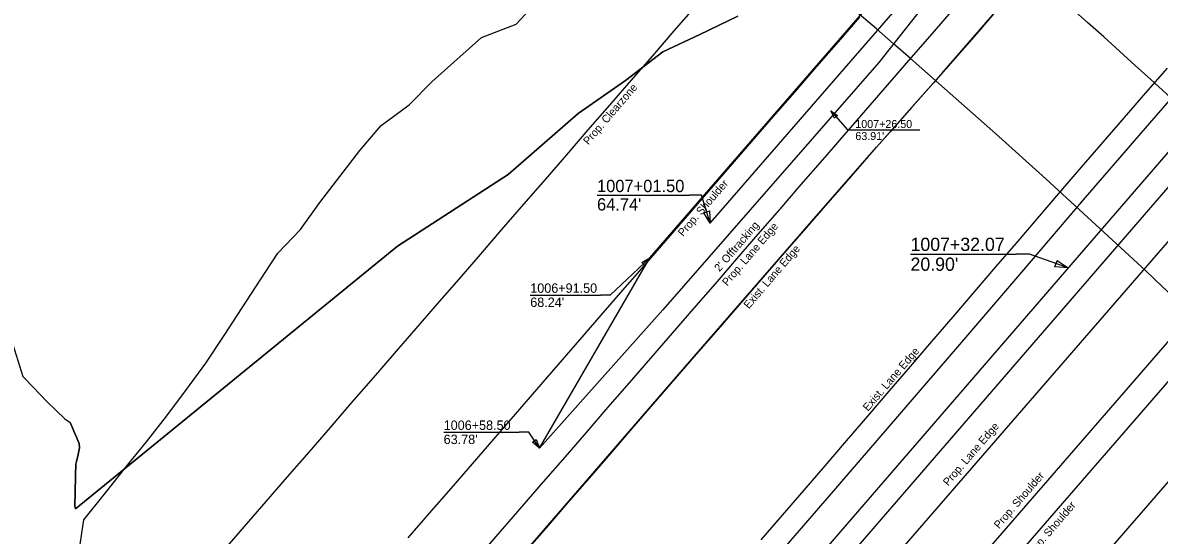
# Model space of a CAD drawing. Extents: x 1006695 to 1009377, y 1883329 to 1886115.
# Drawn here: x 1007700.6 to 1007873.9, y 1884679.4 to 1884757.7 of the extents above; entities that cross this region are included whole.
import ezdxf

# ---------------------------------------------------------------- set-up
doc = ezdxf.new("R2010")
doc.units = 0
for name, color, linetype in [('B_Hatch', 7, 'Continuous'), ('R_I-30 Information', 7, 'Continuous'), ('R_No Plot', 7, 'Continuous'), ('R_Prop Const Limits Cut', 7, 'Continuous'), ('R_Prop EOL', 7, 'Continuous'), ('R_Prop EOS I-30', 7, 'Continuous'), ('R_Prop I-30 Guardrail', 7, 'Continuous')]:
    doc.layers.add(name, color=color, linetype=linetype)

msp = doc.modelspace()

# ---------------------------------------------------------------- linework, layer by layer
at = {"layer": 'B_Hatch'}
for points in [[(1007646.47, 1884785.83), (1007650.32, 1884781.08), (1007657.13, 1884773.48), (1007664.19, 1884766.21), (1007671.31, 1884759.02), (1007678.48, 1884751.9), (1007684.26, 1884742.9), (1007685.68, 1884740.68), (1007687.7, 1884737.51), (1007689.66, 1884734.43), (1007695.24, 1884726.6), (1007697.29, 1884714.24), (1007700.6, 1884703.69), (1007700.97, 1884703.29), (1007704.31, 1884699.79), (1007707.03, 1884697.22), (1007707.84, 1884696.66)], [(1007707.84, 1884696.66), (1007708.2, 1884695.83), (1007708.4, 1884695.35), (1007708.6, 1884694.87), (1007708.81, 1884694.39), (1007709.01, 1884693.91), (1007709.21, 1884693.43), (1007709.27, 1884692.78), (1007709.03, 1884691.74), (1007708.79, 1884690.71), (1007708.7, 1884690.29), (1007708.68, 1884689.84), (1007708.66, 1884689.09), (1007708.65, 1884688.33), (1007708.63, 1884687.58), (1007708.61, 1884686.83), (1007708.59, 1884686.07), (1007708.57, 1884685.32), (1007708.54, 1884684.51), (1007708.54, 1884684.41), (1007708.54, 1884684.3), (1007708.54, 1884684.2), (1007708.53, 1884684.09), (1007708.53, 1884683.99), (1007708.53, 1884683.88), (1007708.63, 1884683.47), (1007757.72, 1884723.55), (1007774.58, 1884734.51), (1007785.28, 1884743.83), (1007792.48, 1884748.84), (1007798.18, 1884753.24), (1007803.81, 1884755.88), (1007809.62, 1884758.64)]]:
    msp.add_lwpolyline(points, dxfattribs=at)
at = {"layer": 'R_I-30 Information'}
for p, q in [((1007780.22, 1884614.59), (1007976.64, 1884841.35)), ((1007787.78, 1884608.04), (1007984.2, 1884834.8)), ((1007790.8, 1884605.42), (1007987.22, 1884832.18)), ((1007798.36, 1884598.88), (1007994.78, 1884825.63))]:
    msp.add_line(p, q, dxfattribs=at)
for points in [[(1007771.8, 1884670.7), (1007781.63, 1884682.03), (1007791.43, 1884693.38), (1007801.23, 1884704.73), (1007820.91, 1884727.36), (1007830.75, 1884738.68), (1007840.72, 1884749.9), (1007850.54, 1884761.25), (1007860.35, 1884772.6), (1007870.16, 1884783.94), (1007879.97, 1884795.28)], [(1007709.06, 1884675.97), (1007709.92, 1884681.82), (1007713.2, 1884685.91), (1007716.33, 1884689.81), (1007719.47, 1884693.71), (1007722.55, 1884697.66), (1007725.54, 1884701.68), (1007728.52, 1884705.72), (1007731.29, 1884709.94), (1007734.05, 1884714.16), (1007736.81, 1884718.39), (1007739.49, 1884722.51), (1007742.96, 1884726.12), (1007745.87, 1884730.21), (1007748.93, 1884734.18), (1007751.99, 1884738.15), (1007755.23, 1884741.95), (1007759.49, 1884745.13), (1007763.02, 1884748.69), (1007766.8, 1884752.03), (1007770.55, 1884755.39), (1007775.84, 1884757.42), (1007779.23, 1884761.1)], [(1007803.14, 1884760.19), (1007799.87, 1884756.41), (1007796.6, 1884752.63), (1007793.32, 1884748.85), (1007790.05, 1884745.07), (1007786.77, 1884741.29), (1007783.5, 1884737.51), (1007780.23, 1884733.73), (1007776.95, 1884729.95), (1007773.6, 1884726.09), (1007770.33, 1884722.31), (1007767.06, 1884718.53), (1007763.78, 1884714.75), (1007760.51, 1884710.97), (1007757.23, 1884707.19), (1007754.01, 1884703.47), (1007750.74, 1884699.69), (1007747.46, 1884695.91), (1007744.19, 1884692.13), (1007740.92, 1884688.35), (1007737.64, 1884684.57), (1007734.37, 1884680.79), (1007731.1, 1884677.01)], [(1007849.3, 1884759.82), (1007846.03, 1884756.03), (1007842.76, 1884752.25), (1007839.47, 1884748.49), (1007836.14, 1884744.75), (1007832.82, 1884741.01), (1007829.51, 1884737.26), (1007826.23, 1884733.49), (1007822.95, 1884729.72), (1007819.67, 1884725.94), (1007816.39, 1884722.17), (1007813.11, 1884718.4), (1007809.83, 1884714.62), (1007806.55, 1884710.85), (1007803.27, 1884707.07), (1007800, 1884703.3), (1007796.73, 1884699.51), (1007793.46, 1884695.73), (1007790.19, 1884691.94), (1007786.93, 1884688.16), (1007783.66, 1884684.37), (1007780.39, 1884680.59), (1007777.11, 1884676.82)], [(1007828.17, 1884758.53), (1007824.89, 1884754.75), (1007821.62, 1884750.97), (1007818.24, 1884747.07), (1007814.96, 1884743.29), (1007811.69, 1884739.51), (1007808.42, 1884735.73), (1007805.14, 1884731.95), (1007801.87, 1884728.17), (1007798.59, 1884724.39), (1007795.32, 1884720.61), (1007792.05, 1884716.83), (1007788.74, 1884713.02), (1007785.47, 1884709.24), (1007782.19, 1884705.46), (1007778.92, 1884701.68), (1007775.65, 1884697.9), (1007772.37, 1884694.12), (1007769.12, 1884690.36), (1007765.85, 1884686.58), (1007762.57, 1884682.81), (1007759.3, 1884679.03)], [(1007842.14, 1884759.39), (1007838.87, 1884755.61), (1007835.64, 1884751.89), (1007832.37, 1884748.11), (1007829.09, 1884744.33), (1007825.78, 1884740.51), (1007822.51, 1884736.73), (1007819.24, 1884732.95), (1007815.96, 1884729.17), (1007812.69, 1884725.39), (1007809.42, 1884721.61), (1007806.14, 1884717.83), (1007802.87, 1884714.05), (1007799.59, 1884710.27), (1007796.31, 1884706.48), (1007793.04, 1884702.7), (1007789.76, 1884698.92), (1007786.49, 1884695.14), (1007783.22, 1884691.36), (1007779.94, 1884687.58), (1007776.68, 1884683.81), (1007773.4, 1884680.03), (1007770.13, 1884676.25)], [(1007875.07, 1884750.75), (1007871.79, 1884746.97), (1007868.52, 1884743.19), (1007865.24, 1884739.42), (1007861.96, 1884735.64), (1007858.48, 1884731.59), (1007855.23, 1884727.78), (1007851.98, 1884723.98), (1007848.92, 1884720.39), (1007845.66, 1884716.6), (1007842.41, 1884712.8), (1007839.16, 1884709.01), (1007835.9, 1884705.21), (1007832.65, 1884701.42), (1007829.39, 1884697.62), (1007826.13, 1884693.83), (1007822.88, 1884690.03), (1007819.67, 1884686.31), (1007816.39, 1884682.53), (1007813.11, 1884678.76)]]:
    msp.add_lwpolyline(points, dxfattribs=at)
at = {"layer": 'R_No Plot'}
for p, q in [((1007827.53, 1884741.29), (1007837.34, 1884741.29)), ((1007788.15, 1884731.35), (1007802.22, 1884731.35)), ((1007835.94, 1884722.33), (1007852.07, 1884722.33)), ((1007777.97, 1884716.08), (1007788.7, 1884716.08)), ((1007764.77, 1884695.16), (1007776.3, 1884695.16))]:
    msp.add_line(p, q, dxfattribs=at)
for points in [[(1007823.8, 1884744.2), (1007826.31, 1884741.29), (1007827.53, 1884741.29)], [(1007805.4, 1884727.06), (1007804.09, 1884731.35), (1007802.22, 1884731.35)], [(1007796.21, 1884721.79), (1007790.13, 1884716.08), (1007788.7, 1884716.08)], [(1007859.96, 1884720.24), (1007854.09, 1884722.33), (1007852.07, 1884722.33)], [(1007779.38, 1884692.71), (1007777.74, 1884695.16), (1007776.3, 1884695.16)]]:
    msp.add_lwpolyline(points, dxfattribs=at)
for points in [[(1007823.8, 1884744.2), (1007824.8, 1884743.49), (1007824.35, 1884743.11)], [(1007805.4, 1884727.06), (1007804.44, 1884728.66), (1007805.31, 1884728.93)], [(1007796.21, 1884721.79), (1007795.43, 1884720.58), (1007794.96, 1884721.09)], [(1007859.96, 1884720.24), (1007857.95, 1884720.43), (1007858.28, 1884721.36)], [(1007779.38, 1884692.71), (1007778.32, 1884693.67), (1007778.89, 1884694.06)]]:
    msp.add_lwpolyline(points, close=True, dxfattribs=at)
at = {"layer": 'R_Prop Const Limits Cut'}
for points in [[(1007662.37, 1884768.08), (1007664.19, 1884766.21), (1007671.31, 1884759.02), (1007678.48, 1884751.9), (1007684.26, 1884742.9), (1007685.68, 1884740.68), (1007687.7, 1884737.51), (1007689.66, 1884734.43), (1007695.24, 1884726.6), (1007697.29, 1884714.24), (1007700.6, 1884703.69), (1007700.97, 1884703.29), (1007704.31, 1884699.79), (1007707.03, 1884697.22), (1007707.84, 1884696.66)], [(1007809.62, 1884758.64), (1007803.81, 1884755.88), (1007798.18, 1884753.24), (1007792.48, 1884748.84), (1007785.28, 1884743.83), (1007774.58, 1884734.51), (1007757.72, 1884723.55), (1007708.63, 1884683.47), (1007708.53, 1884683.88), (1007708.53, 1884683.9), (1007708.53, 1884683.91), (1007708.53, 1884683.93), (1007708.53, 1884683.94), (1007708.53, 1884683.96), (1007708.53, 1884683.97), (1007708.53, 1884683.99), (1007708.53, 1884684), (1007708.53, 1884684.02), (1007708.53, 1884684.03), (1007708.53, 1884684.05), (1007708.53, 1884684.06), (1007708.53, 1884684.08), (1007708.53, 1884684.09), (1007708.53, 1884684.11), (1007708.53, 1884684.12), (1007708.53, 1884684.14), (1007708.53, 1884684.15), (1007708.54, 1884684.17), (1007708.54, 1884684.18), (1007708.54, 1884684.2), (1007708.54, 1884684.21), (1007708.54, 1884684.23), (1007708.54, 1884684.24), (1007708.54, 1884684.26), (1007708.54, 1884684.27), (1007708.54, 1884684.29), (1007708.54, 1884684.3), (1007708.54, 1884684.32), (1007708.54, 1884684.33), (1007708.54, 1884684.35), (1007708.54, 1884684.36), (1007708.54, 1884684.38), (1007708.54, 1884684.39), (1007708.54, 1884684.41), (1007708.54, 1884684.42), (1007708.54, 1884684.44), (1007708.54, 1884684.45), (1007708.54, 1884684.47), (1007708.54, 1884684.48), (1007708.54, 1884684.5), (1007708.54, 1884684.51), (1007708.54, 1884684.53), (1007708.55, 1884684.54), (1007708.55, 1884684.56), (1007708.55, 1884684.57), (1007708.57, 1884685.32), (1007708.59, 1884686.07), (1007708.61, 1884686.83), (1007708.63, 1884687.58), (1007708.65, 1884688.33), (1007708.66, 1884689.09), (1007708.68, 1884689.84), (1007708.7, 1884690.29), (1007708.79, 1884690.71), (1007709.03, 1884691.74), (1007709.27, 1884692.78), (1007709.21, 1884693.43), (1007709.01, 1884693.91), (1007708.81, 1884694.39), (1007708.6, 1884694.87), (1007708.4, 1884695.35), (1007708.2, 1884695.83), (1007707.84, 1884696.66)]]:
    msp.add_lwpolyline(points, dxfattribs=at)
at = {"layer": 'R_Prop EOL'}
for radius, start in [(1443.39, 37.04506), (1421.39, 35.65164)]:
    msp.add_arc((1006901.08, 1883681.49), radius, start, 53.47197, dxfattribs=at)
at = {"layer": 'R_Prop EOS I-30'}
for p, q in [((1007796.21, 1884721.79), (1008022.13, 1884982.53)), ((1007789.1, 1884632.79), (1008066.81, 1884954.51)), ((1007779.38, 1884692.71), (1007796.21, 1884721.79))]:
    msp.add_line(p, q, dxfattribs=at)
for points in [[(1008059.19, 1884957.52), (1008049.41, 1884946.15), (1008039.63, 1884934.78), (1008029.82, 1884923.41), (1008020, 1884912.07), (1008010.19, 1884900.73), (1008000.37, 1884889.39), (1007990.55, 1884878.06), (1007970.91, 1884855.39), (1007961.08, 1884844.06), (1007951.25, 1884832.73), (1007941.42, 1884821.41), (1007931.56, 1884810.09), (1007921.65, 1884798.82), (1007911.75, 1884787.56), (1007901.86, 1884776.3), (1007892.04, 1884764.98), (1007882.22, 1884753.65), (1007872.39, 1884742.32), (1007862.59, 1884731.01), (1007852.86, 1884719.61), (1007843.09, 1884708.22), (1007823.56, 1884685.45), (1007813.72, 1884674.12)], [(1007839.35, 1884762.05), (1007831.13, 1884751.61), (1007798.17, 1884713.86), (1007779.38, 1884692.71)]]:
    msp.add_lwpolyline(points, dxfattribs=at)
at = {"layer": 'R_Prop I-30 Guardrail'}
for p, q in [((1008113.17, 1885013.57), (1007737.44, 1884578.31)), ((1007805.4, 1884727.06), (1008018.22, 1884972.68))]:
    msp.add_line(p, q, dxfattribs=at)

# ---------------------------------------------------------------- texts
at = {"layer": 'R_I-30 Information'}
for s, p in [('Prop. Clearzone', (1007786.83, 1884738.93)), ('Prop. Shoulder', (1007801.27, 1884724.95)), ("2' Offtracking", (1007806.82, 1884719.58)), ('Prop. Lane Edge', (1007808, 1884717.39)), ('Exist. Lane Edge', (1007811.29, 1884713.91)), ('Exist. Lane Edge', (1007829.46, 1884698.28)), ('Prop. Lane Edge', (1007841.68, 1884686.88)), ('Prop. Shoulder', (1007849.44, 1884680.35)), ('Prop. Shoulder', (1007854.24, 1884675.84))]:
    msp.add_text(s, height=1.2, rotation=49.3699, dxfattribs=at).set_placement(p)
at = {"layer": 'R_No Plot'}
for s, height, p in [('1007+26.50', 1.22, (1007827.53, 1884741.59)), ("63.91'", 1.22, (1007827.53, 1884739.76)), ('1007+01.50', 1.875, (1007788.15, 1884731.81)), ("64.74'", 1.875, (1007788.15, 1884729)), ('1007+32.07', 2.022, (1007835.94, 1884722.83)), ("20.90'", 2.022, (1007835.94, 1884719.8)), ('1006+91.50', 1.436, (1007777.97, 1884716.44)), ("68.24'", 1.436, (1007777.97, 1884714.28)), ('1006+58.50', 1.436, (1007764.77, 1884695.52)), ("63.78'", 1.436, (1007764.77, 1884693.36))]:
    msp.add_text(s, height=height, dxfattribs=at).set_placement(p)

doc.saveas('drawing.dxf')
